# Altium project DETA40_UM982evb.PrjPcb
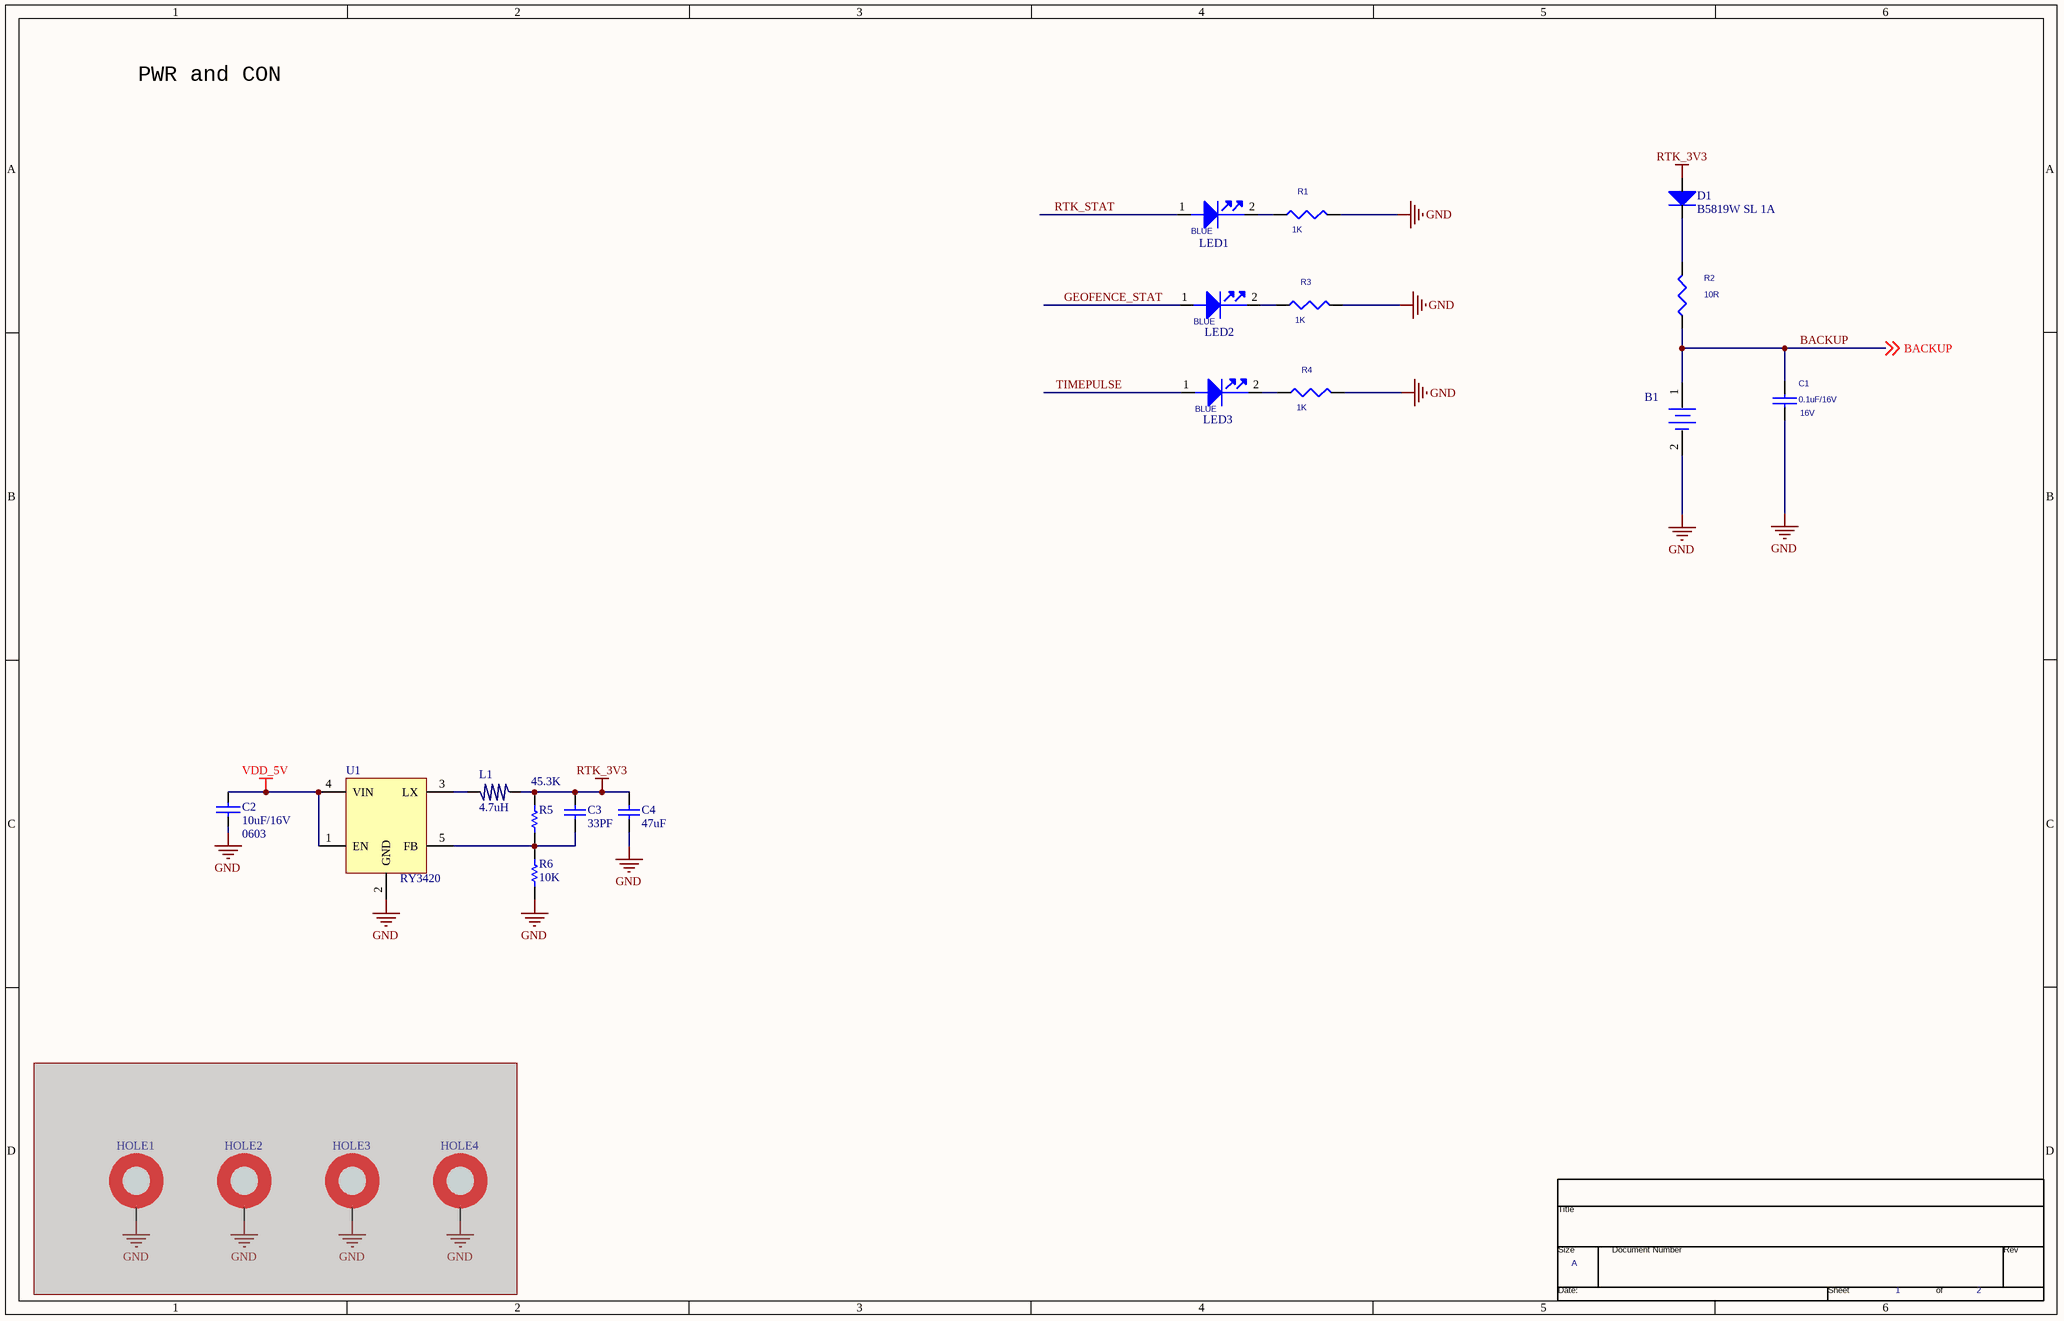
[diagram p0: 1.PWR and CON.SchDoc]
3 sheets, 62 parts. Net scope: global (net labels, ports and power ports of the same name join across sheets).
Board file: DETA40N_982_V1_20260630.PcbDoc
Sheets:
  1.PWR and CON.SchDoc
  2.ZED-F9P_1ANT.SchDoc
  3.FEIMA_DETA30CPU.SchDoc

## Sheet 1.PWR and CON.SchDoc
size 386 x 246 mm

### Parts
(Parts that share a designator on the sheet are numbered #1, #2 ... from top to bottom, then left to right.)
*  Page Count: 2  Page Number: 1  Page Size: A  (hidden comment: TitleBlock0)  (graphical)
B1  XH414  [XH414]  (value not drawn)
C1  0.1uF/16V  ASSY_OPT: 16V  [C0402]
C2  Type: 0603  [C0603]  (hidden comment: 10uF/16V)
C3  33PF  [C0402]
C4  47uF  [C0805]
D1  B5819W SL 1A  [SOD-323]
HOLE1  HOLE  [HOLE-3.0]  (value not drawn)  (masked out: inside a compile mask, not in the netlist)
HOLE2  HOLE  [HOLE-3.0]  (value not drawn)  (masked out: inside a compile mask, not in the netlist)
HOLE3  HOLE  [HOLE-3.0]  (value not drawn)  (masked out: inside a compile mask, not in the netlist)
HOLE4  HOLE  [HOLE-3.0]  (value not drawn)  (masked out: inside a compile mask, not in the netlist)
L1#1  4.7uH  [铁氧体贴片电感3*3LQH3NPN - duplicate1]
LED1  BLUE  [LED_0603_BLUE]
LED2  BLUE  [LED_0603_BLUE]
LED3  BLUE  [LED_0603_BLUE]
R1  1K  [RES0402]
R2  10R  [RES0402]
R3  1K  [RES0402]
R4  1K  [RES0402]
R5#1  45.3K  [RES0402]
R6#1  value 10K  [RES0402]  (hidden comment: 16.2K)
U1  RY3420  [SOT23-5]

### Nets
GND: B1.2 C1.1 C2.2 C4.1 R1.2 R3.2 R4.2 R6#1.1 U1.2(GND)
RTK_3V3: C3.2 C4.2 D1.1 L1#1.1 R5#1.2
VDD_5V: C2.1 U1.1(EN) U1.4(VIN)
BACKUP: B1.1 C1.2 R2.1 ; off-sheet BACKUP
GEOFENCE_STAT: LED2.1(ANODE)
RTK_STAT: LED1.1(ANODE)
TIMEPULSE: LED3.1(ANODE)
NetC3_1: C3.1 R5#1.1 R6#1.2 U1.5(FB)
NetD1_2: D1.2 R2.2
NetL1#1_2: L1#1.2 U1.3(LX)
NetLED1_2: LED1.2(CATHODE) R1.1
NetLED2_2: LED2.2(CATHODE) R3.1
NetLED3_2: LED3.2(CATHODE) R4.1

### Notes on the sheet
- PWR and CON

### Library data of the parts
B1 = MS621FE-FL11E: Part Description: 钮扣电池
C1 = CAP C0402 DNP
C2 = C1
C3 C4 = Cap: Capacitor
D1 = 1n5819ws
L1#1 = L
LED1-LED3 = 19-217-BHC-XL2M2TY-3T-AM_1: 白发蓝; Part number: 100102000023; SolderType: SMD; SPEC: 0603; MFG: Everlight; Type: LED; STD: AUTO
R1 R3 R4 = R: 贴片电阻，1K，5%，1/16W，0402，FH; Part number: 110120100430; Part: RC-02W102JT; SPEC: R0402; MFG: FH
R2 = RES 10K,5%,1/16W,0402: Part number: '108012200014; Part: RC-02W103JT; SPEC: R0402; STD: industry; SolderType: SMD; MFG: FH
R5#1 R6#1 = Res1: Resistor
U1 = SY8088AAC

## Sheet 2.ZED-F9P_1ANT.SchDoc
size A2
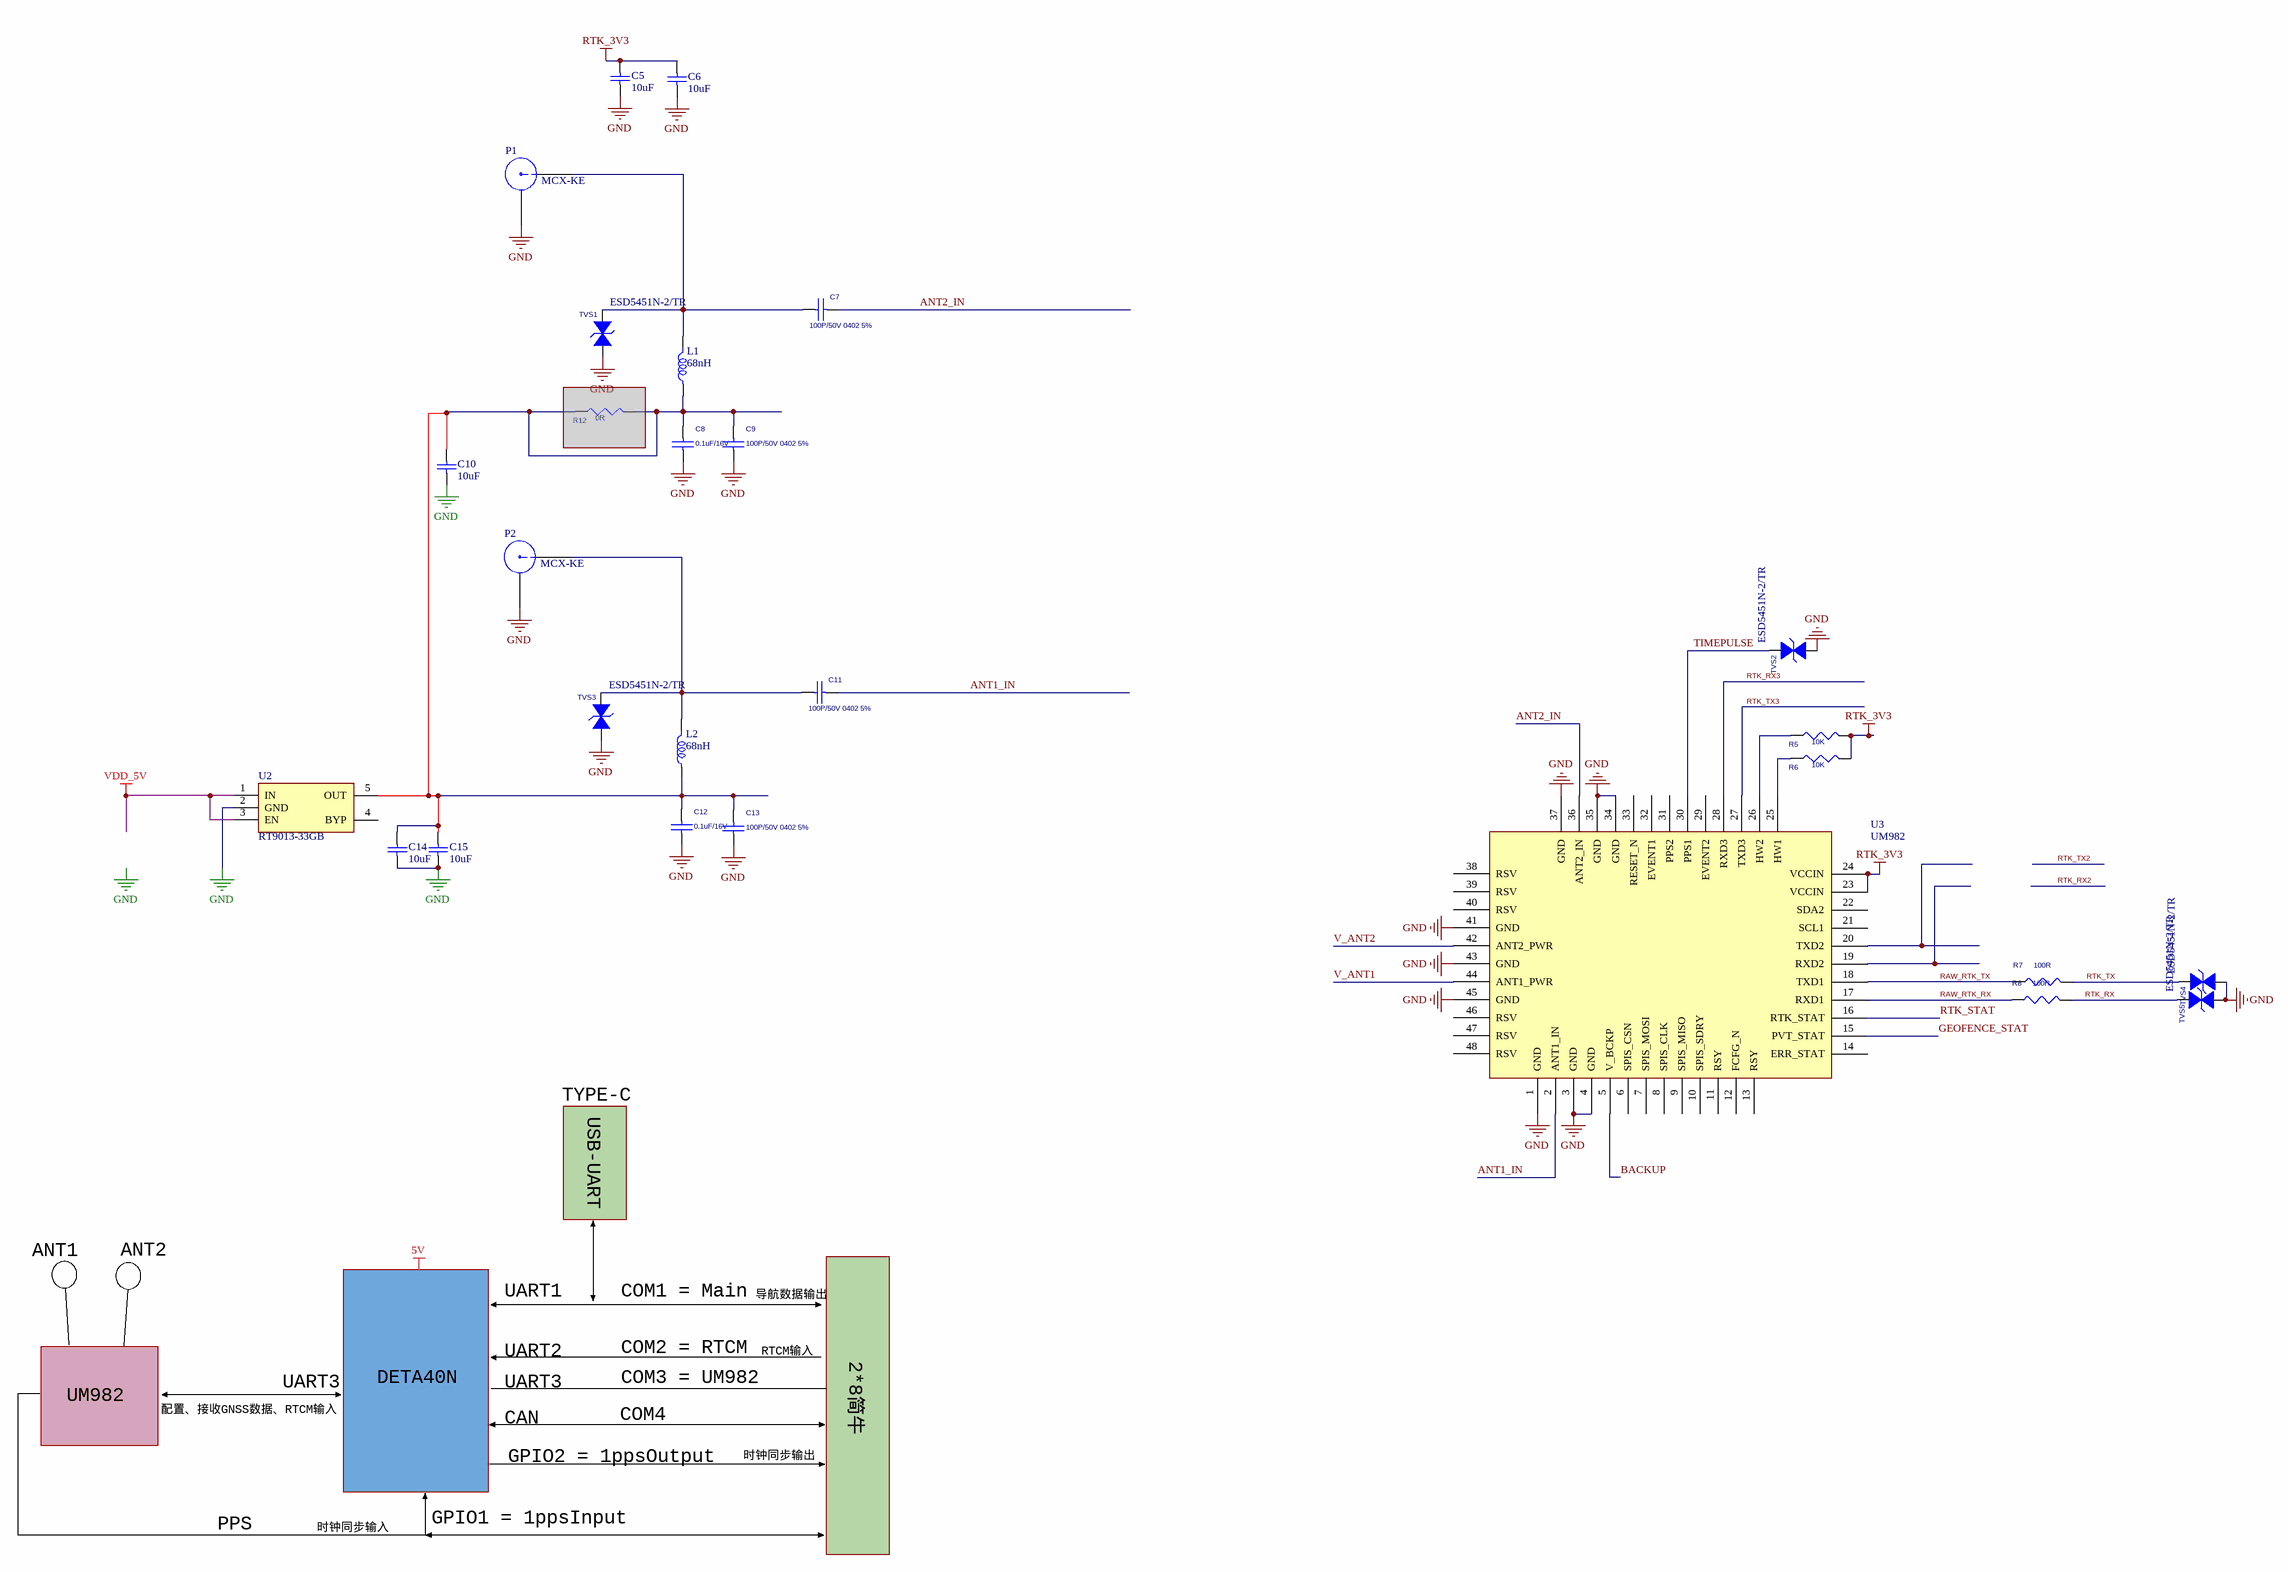
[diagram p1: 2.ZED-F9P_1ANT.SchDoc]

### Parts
(Parts that share a designator on the sheet are numbered #1, #2 ... from top to bottom, then left to right.)
C5  10uF  [C0603]
C6  10uF  [C0603]
C7  100P/50V 0402 5%  [C0402]
C8  0.1uF/16V  [C0402]
C9  100P/50V 0402 5%  [C0402]
C10  10uF  [C0603]
C11  100P/50V 0402 5%  [C0402]
C12  0.1uF/16V  [C0402]
C13  100P/50V 0402 5%  [C0402]
C14  10uF  [C0603]
C15  10uF  [C0603]
L1#2  68nH  [L0603]
L2  68nH  [L0603]
P1  MCX-KE  [MCX-SMD_KH-MCX-KE-STM]
P2  MCX-KE  [MCX-SMD_KH-MCX-KE-STM]
R5#2  10K  [RES0402]
R6#2  10K  [RES0402]
R7  100R  [RES0402]
R8  100R  [RES0402]
R12#1  0R  [RES0402]  (masked out: inside a compile mask, not in the netlist)
TVS1  ESD5451N-2/TR  [ESD_0402]
TVS2  ESD5451N-2/TR  [ESD_0402]
TVS3  ESD5451N-2/TR  [ESD_0402]
TVS4  ESD5451N-2/TR  [ESD_0402]
TVS5  ESD5451N-2/TR  [ESD_0402]
U2  RT9013-33GB  [SOT23-5]
U3  UM982  [UM982]

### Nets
GND: C5.1 C6.1 C8.1 C9.1 C10.1 C12.1 C13.1 C14.1 C15.1 P1.1(GND) P2.1(GND) TVS1.2(I/O2) TVS2.2(I/O2) TVS3.2(I/O2) TVS4.2(I/O2) TVS5.2(I/O2) U2.2(GND) U3.1(GND) U3.3(GND) U3.4(GND) U3.34(GND) U3.35(GND) U3.37(GND) U3.41(GND) U3.43(GND) U3.45(GND)
RTK_3V3: C5.2 C6.2 R5#2.2 R6#2.2 U3.23(VCCIN) U3.24(VCCIN)
VDD_5V: U2.1(IN) U2.3(EN)
ANT1_IN: C11.1 U3.2(ANT1_IN)
ANT2_IN: C7.1 U3.36(ANT2_IN)
BACKUP: U3.5(V_BCKP)
GEOFENCE_STAT: U3.15(PVT_STAT)
RAW_RTK_RX: R8.1 U3.17(RXD1)
RAW_RTK_TX: R7.1 U3.18(TXD1)
RTK_RX: R8.2 TVS5.1(I/O1)
RTK_RX3: U3.28(RXD3)
RTK_STAT: U3.16(RTK_STAT)
RTK_TX: R7.2 TVS4.1(I/O1)
RTK_TX3: U3.27(TXD3)
TIMEPULSE: TVS2.1(I/O1) U3.30(PPS1)
V_ANT1: U3.44(ANT1_PWR)
V_ANT2: U3.42(ANT2_PWR)
NetC7_2: C7.2 L1#2.2 P1.2(ANT) TVS1.1(I/O1)
NetC8_2: C8.2 C9.2 C10.2 C12.2 C13.2 C14.2 C15.2 L1#2.1 L2.1 U2.5(OUT)
NetC11_2: C11.2 L2.2 P2.2(ANT) TVS3.1(I/O1)
NetR5#2_1: R5#2.1 U3.26(HW2)
NetR6#2_1: R6#2.1 U3.25(HW1)

Not connected (* = marked no-connect by the designer): U2 4(BYP); U3 6(SPIS_CSN) 7(SPIS_MOSI) 8(SPIS_CLK) 9(SPIS_MISO) 10(SPIS_SDRY) 11(RSY) 12(FCFG_N) 13(RSY) 14(ERR_STAT) 19(RXD2) 20(TXD2) 21(SCL1) 22(SDA2) 29(EVENT2) 31(PPS2) 32(EVENT1) 33(RESET_N) 38(RSV) 39(RSV) 40(RSV) 46(RSV) 47(RSV) 48(RSV)

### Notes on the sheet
- TYPE-C
- USB-UART
- ANT1
- ANT2
- UART1
- COM1 = Main
- 导航数据输出
- UART2
- COM2 = RTCM
- RTCM输入
- 2*8简牛
- UM982
- 配置、接收GNSS数据、RTCM输入
- UART3
- DETA40N
- CAN
- COM4
- COM3 = UM982
- GPIO2 = 1ppsOutput
- 时钟同步输出
- PPS
- 时钟同步输入
- GPIO1 = 1ppsInput
- Labels drawn without touching a wire or pin: 5V, GND

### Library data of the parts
C5 C6 C10 C14 C15 = Cap1: 贴片瓷介电容
C7-C9 C11-C13 = CAP C0402 DNP
L1#2 L2 = Inductor: 高频贴片电感
P1 P2 = IPEX _Antenna: MCX-KE 全贴片母座
R5#2 R6#2 R7 R8 R12#1 = RES 1K,5%,1/16W,0402CC: 贴片电阻,10R,5%,1/16w,0402,FH3,FH; Part number: 110120100130; Part: RC-02K10R0JT; SPEC: R0402; STD: industry; SolderType: SMD; MFG: YAGEO
TVS1-TVS5 = Varistor_0: 双向400瓦瞬态抑制器/5V; Part: PTUC0521NC; Part number: 110130100560; MFG: PTC
U2 = MIC5205: 500mA Low-Noise LDO Regulator

## Sheet 3.FEIMA_DETA30CPU.SchDoc
size A2
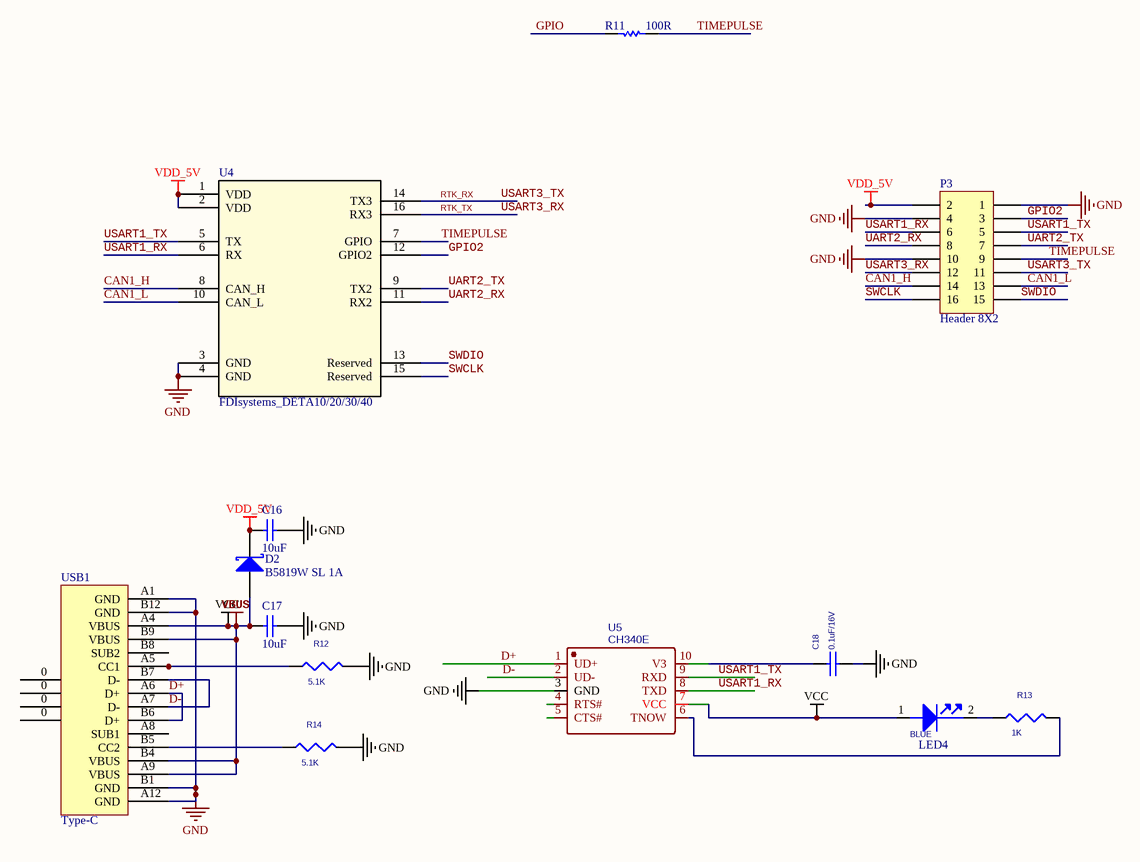
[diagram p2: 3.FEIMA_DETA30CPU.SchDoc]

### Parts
(Parts that share a designator on the sheet are numbered #1, #2 ... from top to bottom, then left to right.)
C16  10uF  [C0603]
C17  10uF  [C0603]
C18  0.1uF/16V  [C0402]
D2  B5819W SL 1A  [SOD-323]
LED4  BLUE  [LED_0603_BLUE]
P3  Header 8X2  [Header_SMD_1.27X8_jianniu - inv]
R11  100R  [RES0402]
R12#2  5.1K  [RES0402]
R13  1K  [RES0402]
R14  5.1K  [RES0402]
U4  FDIsystems_DETA10/20/30/40  [DETA40]
U5  CH340E  [MSOP-10_L3.0-W3.0-P0.50-LS5.0-BL-EP]
USB1  Type-C  [Type-C_Socket_16P]

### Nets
GND: C16.1 C17.1 C18.1 P3.1 P3.4 P3.10 R12#2.2 R14.2 U4.3(GND) U4.4(GND) U5.3(GND) USB1.A1(GND) USB1.A12(GND) USB1.B1(GND) USB1.B12(GND)
VBUS: C17.2 D2.1(A) LED4.1(ANODE) U5.7(VCC) USB1.A4(VBUS) USB1.A9(VBUS) USB1.B4(VBUS) USB1.B9(VBUS)  [also labelled VCC]
VDD_5V: C16.2 D2.2(K) P3.2 U4.1(VDD) U4.2(VDD)
CAN1_H: P3.14 U4.8(CAN_H)
CAN1_L: P3.13 U4.10(CAN_L)
D+: U5.1(UD+) USB1.A6(D+) USB1.B6(D+)
D-: U5.2(UD-) USB1.A7(D-) USB1.B7(D-)
GPIO: R11.1
GPIO2: P3.3 U4.12(GPIO2)
RTK_RX: P3.11 U4.14(TX3)  [also labelled USART3_TX]
RTK_TX: P3.12 U4.16(RX3)  [also labelled USART3_RX]
SWCLK: P3.16 U4.15(Reserved)
SWDIO: P3.15 U4.13(Reserved)
TIMEPULSE: P3.9 R11.2 U4.7(GPIO)
UART2_RX: P3.8 U4.11(RX2)
UART2_TX: P3.7 U4.9(TX2)
USART1_RX: P3.6 U4.6(RX) U5.8(TXD)
USART1_TX: P3.5 U4.5(TX) U5.9(RXD)
NetC18_2: C18.2 U5.10(V3)
NetLED4_2: LED4.2(CATHODE) R13.1
NetR12#2_1: R12#2.1 USB1.A5(CC1)
NetR13_2: R13.2 U5.6(TNOW)
NetR14_1: R14.1 USB1.B5(CC2)

Not connected (* = marked no-connect by the designer): U5 4(RTS#) 5(CTS#); USB1 0 A8(SUB1) B8(SUB2)

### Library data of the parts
C16 C17 = Cap1: 贴片瓷介电容
C18 = CAP C0402 DNP
D2 = D Schottky
LED4 = 19-217-BHC-XL2M2TY-3T-AM_1: as LED1 on sheet 1.PWR and CON
P3 = Header 8X2: Header, 8-Pin, Dual row
R11 = Res1: Resistor; Value: 1K
R12#2 R14 = R: 贴片电阻，5.1K，5%，1/16W，0402，FH; Part number: 110120100430; Part: RC-02W102JT; SPEC: R0402; MFG: FH
R13 = R: as R1 on sheet 1.PWR and CON
U4 = FDI_DETA30AN
U5 = CH340E: Manufacturer: WCH; subpart_no: 1
USB1 = Type-C Socket: USB 3.1  单排16PIN四脚插板(L=7.35) 一体式MD

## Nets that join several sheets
GND: 1.PWR and CON (9 pins), 2.ZED-F9P_1ANT (26 pins), 3.FEIMA_DETA30CPU (15 pins)
RTK_3V3: 1.PWR and CON (5 pins), 2.ZED-F9P_1ANT (6 pins)
VDD_5V: 1.PWR and CON (C2.1 U1.1 U1.4), 2.ZED-F9P_1ANT (U2.1 U2.3), 3.FEIMA_DETA30CPU (5 pins)
BACKUP: 1.PWR and CON (B1.1 C1.2 R2.1), 2.ZED-F9P_1ANT (U3.5)
GEOFENCE_STAT: 1.PWR and CON (LED2.1), 2.ZED-F9P_1ANT (U3.15)
RTK_RX: 2.ZED-F9P_1ANT (R8.2 TVS5.1), 3.FEIMA_DETA30CPU (P3.11 U4.14)
RTK_STAT: 1.PWR and CON (LED1.1), 2.ZED-F9P_1ANT (U3.16)
RTK_TX: 2.ZED-F9P_1ANT (R7.2 TVS4.1), 3.FEIMA_DETA30CPU (P3.12 U4.16)
TIMEPULSE: 1.PWR and CON (LED3.1), 2.ZED-F9P_1ANT (TVS2.1 U3.30), 3.FEIMA_DETA30CPU (P3.9 R11.2 U4.7)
